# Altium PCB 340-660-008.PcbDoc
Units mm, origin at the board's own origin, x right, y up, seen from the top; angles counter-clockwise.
Board outline 21.35 x 16.64 mm, 2 copper layers (Top Layer, Bottom Layer), stack 1.569 mm thick; 37 components, 29 nets, 121 pads, 45 vias.
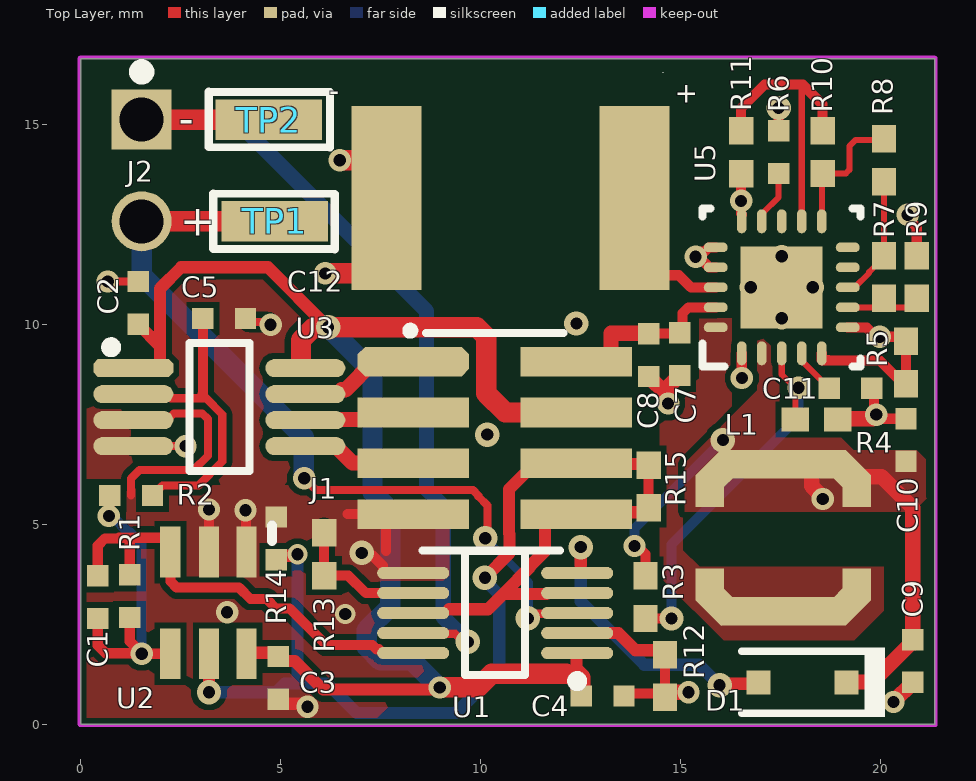
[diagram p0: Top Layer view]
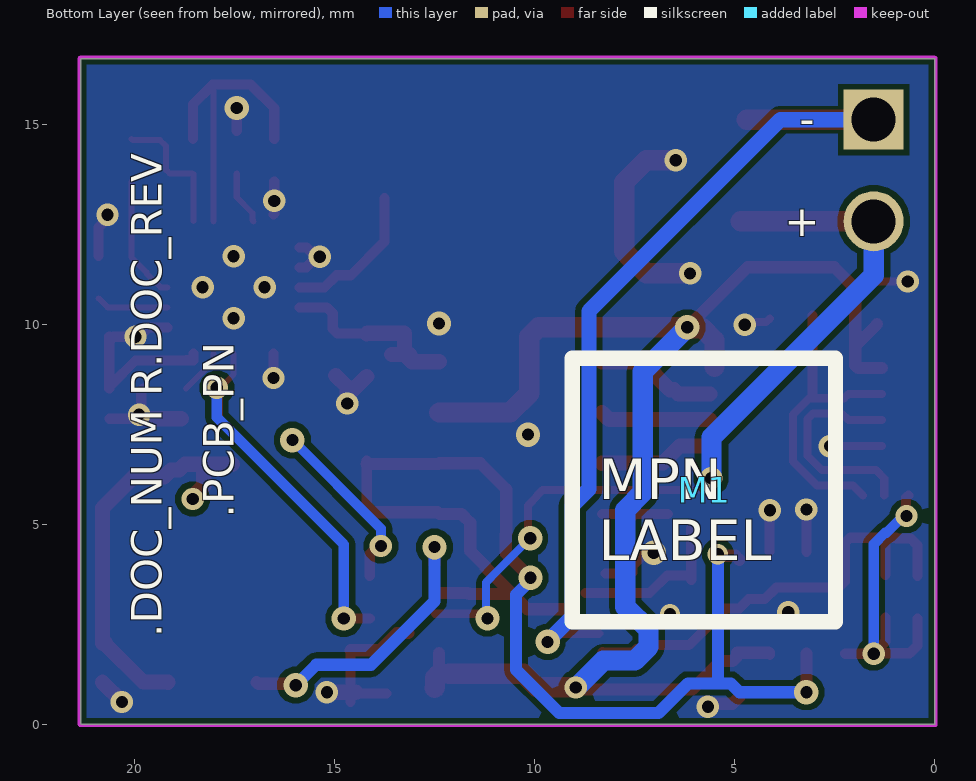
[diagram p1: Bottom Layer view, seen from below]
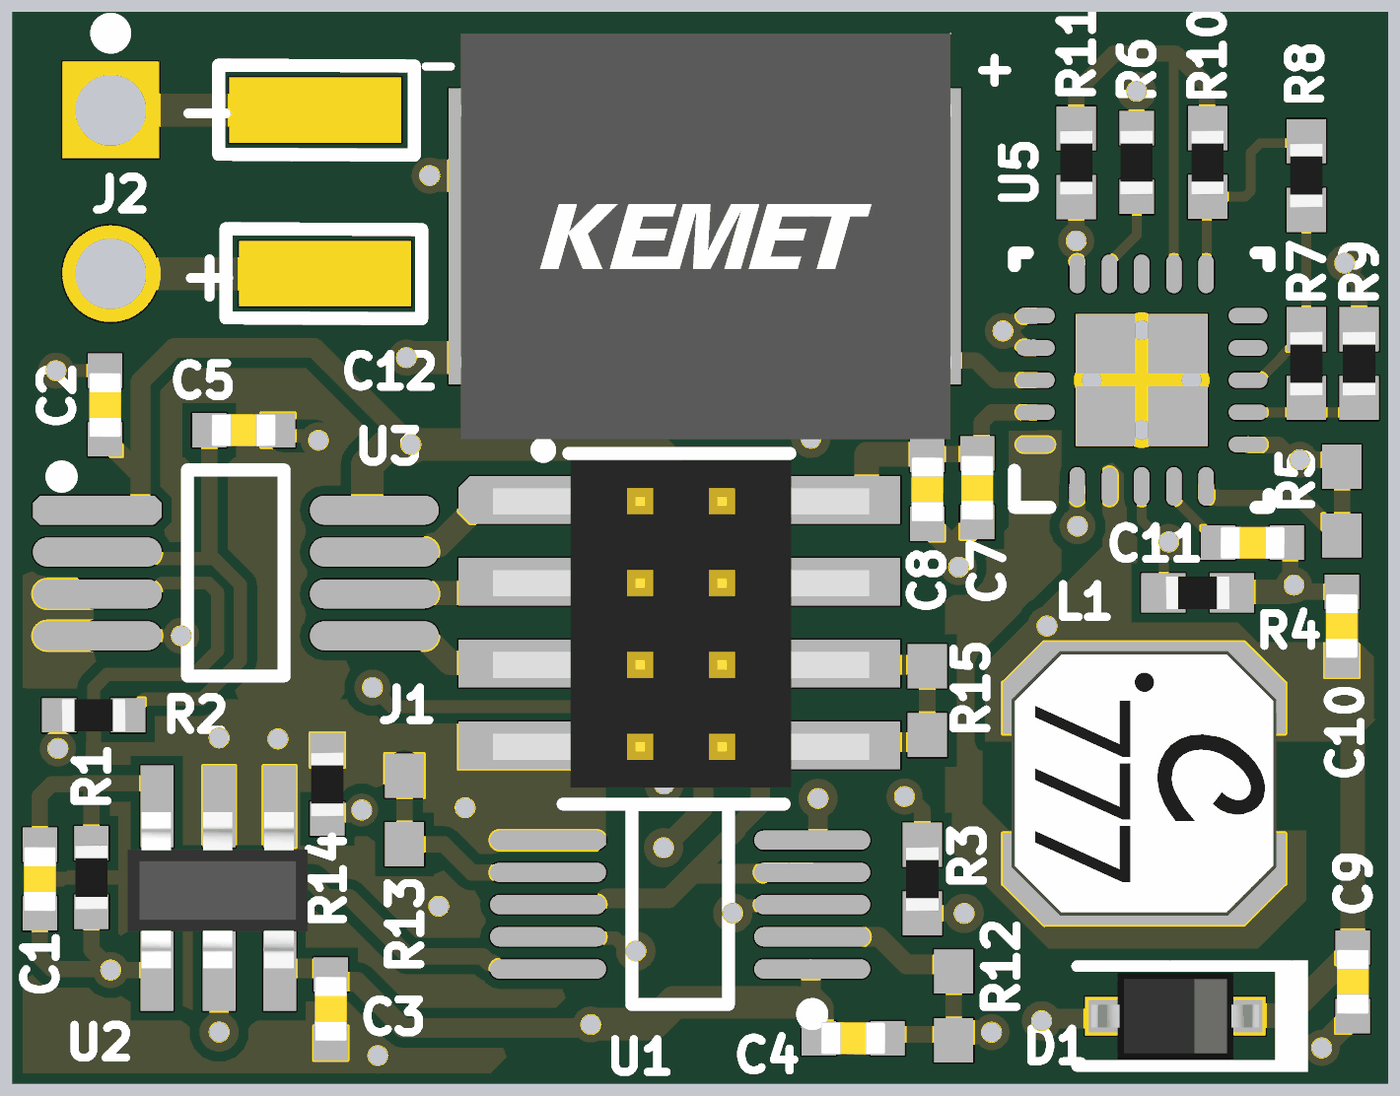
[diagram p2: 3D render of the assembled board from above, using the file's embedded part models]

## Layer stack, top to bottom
Top Solder: solder mask 0.0254, SM-001, Dk 4
Top Layer: signal copper 0.035
Dielectric 1: core 1.4986, Core-043, Dk 4.3
Bottom Layer: signal copper 0.035
Bottom Solder: solder mask 0.0254, SM-001, Dk 4

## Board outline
0,0 0,16.637 21.349,16.637 21.349,0

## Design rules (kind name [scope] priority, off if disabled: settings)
AssemblyTestPointUsage [All] p1 off:
AssemblyTestpoint [All] p1 off: testpointundercomponent=TRUE minsize=1.016 maxsize=2.54 preferedsize=1.524 minholesize=0 maxholesize=1.016 preferedholesize=0.813 testpointgrid=0.025 usegrid=TRUE gridtolerance=0 allowsidetop=TRUE allowsidebottom=TRUE
Clearance [All] p1: gap=0.152 ignorepadtopadclearanceinfootprint=TRUE except(0.127: Arc-Arc Arc-Track Arc-SMDPad Track-Track Track-SMDPad)
ComponentClearance [Not(HasFootprint('FID_TOP_BOT_39'))] p1: gap=0.254 collisioncheckmode=3 verticalgap=0 showdistances=FALSE
DiffPairsRouting [InDifferentialPairClass('All Differential Pairs')] p1: maxlimit=0.127 minlimit=0.127 mostfreqgap=0.127 toplayer_minwidth=0.203 toplayer_maxwidth=0.234 toplayer_prefwidth=0.179 bottomlayer_minwidth=0.203 bottomlayer_maxwidth=0.234 bottomlayer_prefwidth=0.179 impedanceprofiledriven=TRUE maxuncoupledlength=12.7
FabricationTestPointUsage [All] p1 off: valid=0 allowmultiple=FALSE
FabricationTestpoint [All] p1 off: side=3 testpointundercomponent=TRUE minsize=1.016 maxsize=2.54 preferedsize=1.524 minholesize=0 maxholesize=1.016 preferedholesize=0.813 testpointgrid=0.025 allowsidetop=TRUE allowsidebottom=TRUE usegrid=TRUE gridtolerance=0
HoleSize [All] p1: absolutevalues=TRUE maxlimit=5.08 minlimit=0.025 maxpercent=80.000 minpercent=20.000
HoleSize Testpoint [All] p2 off: absolutevalues=TRUE maxlimit=2.54 minlimit=0.025 maxpercent=80.000 minpercent=20.000
HoleSize TestPointUsage [All] p3 off: absolutevalues=TRUE maxlimit=2.54 minlimit=0.025 maxpercent=80.000 minpercent=20.000
MinimumAnnularRing [All] p1: minimumring=0.124
MinimumSolderMaskSliver [All] p1 off: minsoldermaskwidth=0.15
MinimumSolderMaskSliver SilkscreenOverComponentPads [All] p2 off: minsoldermaskwidth=0.254
NetAntennae [All] p1: netantennaetolerance=0.254
PlaneClearance [All] p1: clearance=0.381
PlaneConnect [All] p1: planeconnectstyle=Direct reliefexpansion=0.508 reliefentries=4 reliefconductorwidth=0.762 reliefairgap=0.254
PolygonConnect PolygonConnect_ConnectorPad [HasFootprint('JST_SM06B_SIDE') Or HasFootprint('JST_SM04B_SIDE')Or HasFootprint('JST_SM03B_SIDE') Or HasFootprint('JST_SM02B_SIDE') Or HasFootprint('JST_BM04B_TOP')] p1: connectstyle=Relief reliefconductorwidth=0.762 reliefentries=4 polygonreliefangle="90 Angle" airgapwidth=0.254
PolygonConnect [All] p2: connectstyle=Direct reliefconductorwidth=0.762 reliefentries=4 polygonreliefangle="45 Angle" airgapwidth=0.254
RoutingVias [All] p1: holewidth=0.305 width=0.66 viastyle="Through Hole" minholewidth=0.254 minwidth=0.508 maxholewidth=0.508 maxwidth=1.27
SilkToSilkClearance [All] p1 off: silktosilkclearance=0.254
SilkToSolderMaskClearance [IsPad] p1 off: minsilkscreentomaskgap=0.254 clearancetoexposedcopper=TRUE
SolderMaskExpansion [All] p1: expansion=0.025 istentingtop=FALSE
SupplyNets "Schematic Supply Nets" [InNet('GND')] p1: voltage=0.000
Width [All] p1: maxlimit=5.08 minlimit=0.152 preferedwidth=0.254 minimp=50.000000 maximp=50.000000 favimp=50.000000
17 further rules are at their usual default settings.

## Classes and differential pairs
component class S6: A1 M1 Z1
component class S5: C7 C8 C9 C10 C11 C12 D1 L1 R3 R4 R5 R6 R7 R8 R9 R10 R11 U5
component class S4: C1 C2 C3 C4 C5 R1 R2 R12 R13 R14 U1 U2 U3
component class 340-660-008: J1 J2 R15 TP1 TP2

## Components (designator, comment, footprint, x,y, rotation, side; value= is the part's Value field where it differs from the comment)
C1 "ECJ-0EC1H221J" 0402CAP 0.425,3.175 r90 top value=220pF
C2 "CL05A226MQ6ZUN8" 0402CAP 1.438,10.535 r270 top value=22uF
C3 "CL05A226MQ6ZUN8" 0402CAP 4.941,1.16 r90 top value=22uF
C4 "C1005X5R1V105K050BC" 0402CAP 13.049,0.703 r180 top value=1.0uF
C5 "ECJ-0EC1H221J" 0402CAP 3.588,10.143 r180 top value=220pF
C7 "GRM155R61A475MEAAD" 0402CAP 14.975,9.25 r270 top value=4.7uF
C8 "GMK105BJ104KV-F" 0402CAP 14.2,9.225 r270 top value=0.1uF
C9 "GRM155R61A475MEAAD" 0402CAP 20.803,1.579 r270 top value=4.7uF
C10 "GMK105BJ104KV-F" 0402CAP 20.633,7.103 r90 top value=0.1uF
C11 "ECJ-0EB1E103K" 0402CAP 19.247,8.396 r0 top value=0.01uF
C12 "T523H108M010APE070" CAP_CASEH 10.757,13.152 r0 top value="1000 uF"
D1 "1SS315TPH3F" sod-323 18.048,1.047 r180 top value=5V
J1 "FTS-104-01-L-DV" CONN_SAMTEC_FTS-104-01-L-DV 10.35,7.793 r270 top
J2 "PEC02SAAN" CONN_PEC02SAAN 1.524,13.843 r270 top
L1 "LPS4018-223MLC" LPS4018 17.562,4.66 r270 top value=22uH
M1 "MPN Label" LABEL_7x7mm 5.75,5.85 r180 bottom
R1 "RC0402FR-07100KL" 0402RES 1.225,3.2 r90 top value=100K
R2 "RC0402FR-07100RL" 0402RES 1.26,5.717 r180 top value=100
R3 "CRCW04024M12FKED" 0402 14.121,3.175 r90 top value=4.12Meg
R4 "CRCW04025M76FKED" 0402 18.395,7.618 r180 top value=5.76Meg
R5 "" 0402_Short 20.633,9.042 r270 top net-tie value=0.0
R6 "CR0402-J/-000GLF" 0402RES 17.447,14.3 r270 top value=0.0
R7 "CRCW04026M19FKED" 0402 20.082,11.177 r90 top value=6.19Meg
R8 "CRCW04023M09FKED" 0402 20.082,14.097 r270 top value=3.09Meg
R9 "CRCW04026M65FKED" 0402 20.9,11.177 r270 top value=6.65Meg
R10 "CRCW04023M57FKED" 0402 18.55,14.3 r270 top value=3.57Meg
R11 "CRCW04026M19FKED" 0402 16.51,14.297 r90 top value=6.19Meg
R12 "" 0402_Short 14.607,1.206 r270 top net-tie value=0.0
R13 "" 0402_Short 6.084,4.247 r90 top net-tie value=0.0
R14 "RC0402FR-07100KL" 0402RES 4.887,4.644 r90 top value=100K
R15 "" 0402_Short 14.199,5.945 r90 top net-tie value=0.0
TP1 "TEST POINT" TPSMTPAD 5.969,12.573 r180 top
TP2 "TEST POINT" TPSMTPAD 3.582,15.113 r0 top
U1 "ADG787BRMZ-500RL7" ADI-RM-10_N 10.362,2.778 r180 top
U2 "MAX9911EXT" SOT-23/6 4.147,4.302 r0 top
U3 "AD7683ARMZRL7" RM-8_M 3.466,7.927 r0 top
U5 "BQ25505RGRR" RGR0020A 17.526,10.921 r90 top

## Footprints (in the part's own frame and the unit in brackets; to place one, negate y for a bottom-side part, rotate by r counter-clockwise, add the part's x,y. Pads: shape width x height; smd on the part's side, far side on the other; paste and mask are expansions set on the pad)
0402 [mil]
  rect 27x24 smd: 1(-21,0) 2(21,0)
  body extent -20,-10 20,10, height 12
0402_Short [mil] "0402 package with PCB short"
  rect 27x24 smd: 1(-21,0) 2(21,0)
  Top Layer lines w10: 25.35,0.03 -25.29,0.03
0402CAP [mil]
  rect 21x21 smd: 1(-21,0) 2(21,0)
  body extent -20,-10 20,10, height 20
0402RES [mil]
  rect 21x21 smd: 1(-21,0) 2(21,0)
  body extent -20,-10 20,10, height 12
ADI-RM-10_N [mm] "SOP, 10-Leads, Body 3x3mm, Pitch 0.5mm, IPC Medium Density"
  oval 1.8x0.3 smd: 1(-2.05,1) 2(-2.05,0.5) 3(-2.05,0) 4(-2.05,-0.5) 5(-2.05,-1) 6(2.05,-1) 7(2.05,-0.5) 8(2.05,0) 9(2.05,0.5) 10(2.05,1)
  silkscreen extent -2.18,-1.55 0.75,1.82, body extent -1.55,-1.55 1.55,1.55, height 1.1
CAP_CASEH [mm]
  rect 1.753x4.6 smd: 1(3.086,0) 2(-3.112,0)
  silkscreen extent 3.8,3.15 3.81,3.15, body extent -3.8,-3.15 3.81,3.15, height 2
CONN_PEC02SAAN [mm] "SULLINS"
  rect 1.5x1.5 hole 1.1: 1(-1.27,0)
  round 1.5 hole 1.1: 2(1.27,0)
  silkscreen extent -2.59,-0.13 -2.34,0.13, body extent -2.54,-1.27 2.54,1.27, height 8.38
CONN_SAMTEC_FTS-104-01-L-DV [mm]
  oct 0.74x2.79 smd: 1(-1.27,-2.035)
  rect 0.74x2.79 smd: 2(-1.27,2.035) 3(0,-2.035) 4(0,2.035) 5(1.27,-2.035) 6(1.27,2.035) 7(2.54,-2.035) 8(2.54,2.035)
  silkscreen extent -2.14,-2.21 3.45,1.72, body extent -1.88,-2.9 3.2,2.95, height 4.29
LABEL_7x7mm [mm] "Box for MPN Lable, 7x7mm"
  silkscreen extent -3.31,-3.29 3.27,3.3
LPS4018 [mil]
  rect 28x123 smd: 1(-72.5,0) 2(72.5,0)
  rect 35.5x28 smd rot 45: 1(-64,64) 2(64.5,-63.5)
  rect 35.5x28 smd rot 135: 1(-64,-64) 2(64,64)
  rect 31.5x28 smd: 1(-46,72.5) 1(-46,-72.5) 2(46,72.5) 2(46,-72.5)
  body extent -81,-81 81,81, height 71
RGR0020A [mm] "QFN, 20-Leads, Body 3.5x3.5mm, Pitch 0.5mm, Thermal Pad 2.05x2.05mm, TI Recommended"
  oval 0.6x0.24 smd: 1(-1.65,1) 2(-1.65,0.5) 3(-1.65,0) 4(-1.65,-0.5) 5(-1.65,-1) 11(1.65,-1) 12(1.65,-0.5) 13(1.65,0) 14(1.65,0.5) 15(1.65,1)
  oval 0.24x0.6 smd: 6(-1,-1.65) 7(-0.5,-1.65) 8(0,-1.65) 9(0.5,-1.65) 10(1,-1.65) 16(1,1.65) 17(0.5,1.65) 18(0,1.65) 19(-0.5,1.65) 20(-1,1.65)
  rect 2.05x2.05 smd paste-1.025: 21(0,0)
  silkscreen extent -1.98,-1.98 1.98,1.98, body extent -1.83,-1.83 1.83,1.83, height 1.01
RM-8_M [mm] "TSOP, 8-Leads, Body 3x3mm, Pitch 0.65mm, IPC Low Density"
  oct 2x0.45 smd: 1(-2.15,0.975)
  oval 2x0.45 smd: 2(-2.15,0.325) 3(-2.15,-0.325) 4(-2.15,-0.975) 5(2.15,-0.975) 6(2.15,-0.325) 7(2.15,0.325) 8(2.15,0.975)
  silkscreen extent -2.83,-1.6 0.75,1.62, body extent -1.6,-1.6 1.6,1.6, height 1.1
sod-323 [mm] "NXP recommended land pattern"
  rect 0.6x0.6 smd paste-0.05: 1(-1.1,0) 2(1.1,0)
  silkscreen extent -2.06,-0.86 1.53,0.86, body extent -1.3,-0.67 1.3,0.68, height 1.1
SOT-23/6 [mil]
  rect 20x50 smd: 1(0,0) 2(-37,0) 3(-75,0) 4(-75,-100) 5(-37,-100) 6(0,-100)
  silkscreen extent 25,11 25,26, body extent -93,-99 17,-3, height 43
TPSMTPAD [mil] "0.105\"x0.040\" rectangular SMT Pad for Test Point"
  rect 105x40 smd paste-27.56: 1(44,0)
  silkscreen extent -15,-27 104,27

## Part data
C1 C5: library part CAP_0402_220pF_NP0_50V, "CAP 220PF 50V CERAMIC 0402 SMD", Supplier Part Number 1=PCC221CQCT-ND, Voltage=50V
C2 C3: library part CAP_0402_22uF_X5R_6.3V, "22µF ±20% 6.3V Ceramic Capacitor X5R 0402 (1005 Metric)", Supplier Part Number 1=1276-6804-1-ND, Voltage=6.3V
C4: library part CAP_0402_1uF_X5R_35V, "CAP CER 1UF 35V X5R 0402", Supplier Part Number 1=810-C1005X5R1V105K, Voltage=35V
C7 C9: library part CAP_0402_4.7uF_X5R_10V, "4.7µF ±20% 10V Ceramic Capacitor X5R 0402 (1005 Metric)", Supplier Part Number 1=490-14306-1-ND, Voltage=10V
C8 C10: library part CAP_0402_0.1uF_X5R_35V, "CAP CER .10UF 35V X5R 0402", Supplier Part Number 1=587-1994-1-ND, Voltage=35V
C11: library part CAP_0402_0.01uF_X7R_25V_2, "CAP .01UF 25V CERAMIC X7R 0402", Supplier Part Number 1=PCC2270CT-ND, Voltage=25V
C12: library part CAP_TANT_CASE_H_1000uF_10V_20%_1, "1000µF Molded Tantalum Polymer Capacitor 10V 2924 (7360 Metric) 70mOhm @ 100kHz", Supplier Part Number 1="Mouser -  80-T523H108M010APE70", Tolerance Rated Capacitance="-20 to 20%", Voltage="10 V"
D1: "Diode, Schottky, 5V, 0.03A, SOD-323", Manufacturer=Toshiba, Supplier Part Number 1=1SS315TPH3FCT-ND, Value1=0.03A, Value2=0.38V
J1: library part CONN_Samtec_FTS-104-01-L-DV, "2x4 0.050\" Surface Mount Micro Terminal Strip", Supplier Part Number 1=SAM13892CT-ND
J2: "Header, 100mil, 2x1, Tin, TH", Manufacturer="Sullins Connector Solutions", Supplier Part Number 1=S1012E-02-ND
L1: library part LPS4018-223MLB, "Inductor, Shielded Drum Core, Ferrite, 22 µH, 0.83 A, 0.36 ohm, SMD", Manufacturer=Coilcraft, Value1="0.36 ohm", Value2=0.83A, ValueDisplayed=22µH
M1: library part Label_MPN, "Serial Number Label Placeholder"
R1 R14: library part Res_0402_100K_1%, "RES 100K OHM 1/16W 1% 0402 SMD", Supplier Part Number 1=311-100KLRCT-ND
R2: library part Res_0402_100_1%_1, "RES SMD 100 OHM 1% 1/16W 0402"
R3: "RES, 4.12 M, 1%, 0.063 W, 0402", Manufacturer=Vishay-Dale, Power_W=0.063, Supplier Part Number 1=541-4.12MLCT-ND, TempCo="100 ppm/C", Tolerance_%=1, Value1=1%, Value2=0.063W, Value_Code=4M12, ValueDisplayed=4.12M
R4: "RES, 5.76 M, 1%, 0.063 W, 0402", Manufacturer=Vishay-Dale, Power_W=0.063, Supplier Part Number 1=71-CRCW04025M76FKED, TempCo="100 ppm/C", Tolerance_%=1, Value1=1%, Value2=0.063W, Value_Code=5M76, ValueDisplayed=5.76M
R5 R12 R13 R15: library part Res_0402_Short, "Resistor footpring with PCB short in footprint; cut to use as regular footprint"
R6: library part Res_0402_0.0_5%_2, "RES ZERO OHM 1/10W 5% 0402 SMD", Supplier Part Number 1=652-CR0402-J/-000GLF
R7 R11: "RES, 6.19 M, 1%, 0.063 W, 0402", Manufacturer=Vishay-Dale, Power_W=0.063, Supplier Part Number 1=71-CRCW04026M19FKED, TempCo="100 ppm/C", Tolerance_%=1, Value1=1%, Value2=0.063W, Value_Code=6M19, ValueDisplayed=6.19M
R8: "RES, 3.09 M, 1%, 0.063 W, 0402", Manufacturer=Vishay-Dale, Power_W=0.063, Supplier Part Number 1=541-3.09MLCT-ND, TempCo="100 ppm/C", Tolerance_%=1, Value1=1%, Value2=0.063W, Value_Code=3M09, ValueDisplayed=3.09M
R9: "RES, 6.65 M, 1%, 0.063 W, 0402", Manufacturer=Vishay-Dale, Power_W=0.063, Supplier Part Number 1=71-CRCW04026M65FKED, TempCo="100 ppm/C", Tolerance_%=1, Value1=1%, Value2=0.063W, Value_Code=6M65, ValueDisplayed=6.65M
R10: "RES, 3.57 M, 1%, 0.063 W, 0402", Manufacturer=Vishay-Dale, Power_W=0.063, Supplier Part Number 1=541-3.57MLCT-ND, TempCo="100 ppm/C", Tolerance_%=1, Value1=1%, Value2=0.063W, Value_Code=3M57, ValueDisplayed=3.57M
TP1 TP2: library part Test_Point_SMT, "Test Point SMT"
U1: library part CMP-0790-00114-1, "2.5 Ohm CMOS Low Power Dual 2:1 Mux / Demux USB 1.1 Switch, -40 to 85 degC, 10-pin SOP (RM-10), Reel", Manufacturer="Analog Devices", Power Dissipation=5.5uW
U2: Package=None
U3: library part CMP-0313-01716-2, "Single 16-Bit PulSAR Analog-to-Digital Converter with Serial, SPI Interface, 100KSPS, -40 to +85 degC, RM-8, Pb-Free, Reel", Generic Part Number=AD7683, Manufacturer="Analog Devices"
U5: "Ultra Low Power Boost Converter with Battery Management for Energy Harvester Applications, RGR0020A", Alternate Manufacturer="Texas Instruments", Alternate PartNumber=BQ25505RGRT

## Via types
v1: diameter 0.559, hole 0.305, Top Layer to Bottom Layer, tented both sides, 29 vias
v2: diameter 0.61, hole 0.305, Top Layer to Bottom Layer, tented both sides, 14 vias
v3: diameter 0.508, hole 0.305, Top Layer to Bottom Layer, tented both sides, 2 vias

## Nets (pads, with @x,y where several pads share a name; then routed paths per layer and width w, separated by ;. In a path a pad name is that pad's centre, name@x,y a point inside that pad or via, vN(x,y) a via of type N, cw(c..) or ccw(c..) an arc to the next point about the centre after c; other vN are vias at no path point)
ENABLE: J1.6 R14.1 R15.2 U2.5 | length 21.6
  Top Layer w0.305: v2(3.207,0.8) U2.5 ; R14.1 4.985,4.209 5.381,4.209 v3(5.42,4.247) ; v2(10.105,3.661) 10.722,4.278 10.722,4.756 10.711,4.767 10.711,5.874 11.36,6.523 J1.6 12.407,6.501 R15.2@14.199,6.501
  Bottom Layer w0.305: v2(3.207,0.8) 4.882,0.8 5.1,1.018 5.501,1.018 ; v3(5.42,4.247) 5.42,1.099 5.501,1.018 ; v2(10.105,3.661) 10.105,3.598 10.465,3.238 10.465,1.361 9.384,0.279 6.903,0.279 6.164,1.018 5.501,1.018
ENABLE2: J1.8 R15.1 U1.4 U1.8 | length 8.3
  Top Layer w0.305: 9.213,2.873 10.18,2.873 10.561,3.255 ; U1.4 11.667,3.278 11.644,3.255 10.561,3.255 ; R15.1 14.16,5.411 14.046,5.298 12.43,5.298 J1.8 11.826,5.253 11.608,5.035 11.608,4.331 11.233,3.956 11.233,3.927 10.561,3.255
GND: C2.1 C3.1 C4.1 C5.1 C7.2 C8.2 C9.2 C10.2 C11.2 C12.2 J1.7 R4.1 R5.1 R6.1 R9.1 R11.1 R12.2 R13.2 R14.2 U1.6 U2.1 U2.2 U3.3 U3.4 U5.1 U5.6 U5.15 U5.16 U5.17 U5.21 | length 32.7
  Top Layer w0.203: v1(0.675,11.068) C2.1 ; 1.26,5.717 1.26,6.147 1.466,6.353 2.823,6.353 3.182,6.712 3.182,7.63 3.04,7.772 2.327,7.772 2.158,7.602 U3.3 ; U3.4 v1(2.62,6.952) ; C5.1 4.21,10.055 4.681,10.055 v1(4.749,9.987)
  Top Layer w0.254: U2.2 v1(3.207,5.367) ; v1(4.12,5.35) 4.133,5.336 U2.1@4.133,4.316 ; 6.666,5.253 J1.7@7.49,5.253 ; v2(7.025,4.281) 7.093,4.213 7.303,4.213 7.554,3.962 7.554,3.8 7.59,3.763 U1.6@8.226,3.763 ; 7.633,4.333 7.633,5.11 J1.7@7.49,5.253 ; J1.7 J1.7@7.49,5.253 ; C4.1@13.71,0.763 R12.2@14.474,0.763 ; v1(15.373,11.685) 15.446,11.685 15.71,11.421 U5.17 ; v1@15.395,11.685 15.531,11.82 15.609,11.82 15.71,11.921 U5.16 ; R11.1@16.51,13.564 16.51,12.764 U5.15@16.53,12.744 ; U5.1 16.526,8.734 16.53,8.73 v1(16.53,8.653) ; R6.1 v2(17.447,15.406) ; U5.6 19.183,9.914 19.653,9.914 19.882,9.685 v1(19.978,9.685) 20.524,9.685 R5.1 ; C11.2 19.835,8.342 19.835,7.793 v1(19.889,7.739) 19.904,7.739 20.006,7.636 C10.2 ; v1(20.678,12.737) 20.678,12.646 20.9,12.424 R9.1
  Top Layer w0.305: C3.1@4.887,0.724 4.887,0.681 5.055,0.512 5.522,0.512 5.6,0.434 v1(5.669,0.434)
  Top Layer w0.381: C8.2 v1@14.651,8.241 ; R12.2@14.474,0.797 v1(15.195,0.797) ; v1(14.685,8.016) 14.685,8.427 C7.2 ; R4.1@18.834,7.636 19.801,7.636 v1@19.904,7.739 ; v1(20.32,0.554) 20.32,0.563 C9.2
  Top Layer w0.508: v1(6.113,11.271) 7.211,11.271 7.757,11.817 7.757,13.551 7.211,14.097 v1(6.475,14.097)
  other v1: 3.66,2.799 17.526,10.146 16.751,10.921 18.301,10.921 17.526,11.696 16.509,13.082
  other v2: 10.166,7.239 12.392,10.017
  other v3: 6.616,2.753
HARVSTR_OUT: C7.1 C8.1 J1.2 U5.19 | length 5
  Top Layer w0.254: C8.1 14.212,9.771 14.935,9.771 15.046,9.883 15.046,10.272 15.195,10.421 U5.19
  Top Layer w0.381: J1.2 13.078,9.063 J1.2@13.257,9.243 ; J1.2@13.123,9.243 J1.2@13.257,9.243 ; J1.2@13.57,9.243 J1.2@13.257,9.243 ; C8.1 14.188,9.771 13.257,9.771 J1.2@13.257,9.243
I_SOL: C1.2 R1.2 U1.10 U2.3 | length 11.4
  Top Layer w0.254: C1.2 0.425,4.464 0.606,4.644 0.948,4.644 0.963,4.66 1.306,4.66 ; R1.2 1.225,4.579 1.306,4.66 ; U1.10@8.3,1.8 8.288,1.787 7.541,1.787 7.454,1.874 7.395,1.874 7.291,1.978 6.139,1.978 5.224,2.894 4.882,2.894 4.648,3.128 4.245,3.128 3.96,3.413 2.402,3.413 2.248,3.568 2.248,4.296 U2.3 2.242,4.533 2.115,4.66 1.306,4.66
LBOOST: L1.2 U5.20
nEN_bq: R5.2 U5.5 | length 2.5
  Top Layer w0.254: U5.5 18.526,9.105 18.533,9.098 18.699,9.098 18.706,9.091 19.978,9.091 R5.2@20.597,8.473
NetD1_2: D1.2 U1.5 | length 7.1
  Top Layer w0.305: 12.501,3.978 12.503,3.981 v2(12.503,4.426) ; v2(15.972,0.975) 16.009,1.011 16.912,1.011 D1.2
  Bottom Layer w0.305: v2(12.503,4.426) 12.503,3.073 14.089,1.488 15.459,1.488 v2(15.972,0.975)
NetJ1_1: J1.1 U3.7 | length 3
  Top Layer w0.381: U3.7 6.41,8.252 6.517,8.36 6.616,8.36 7.319,9.063 J1.1
NetJ1_3: J1.3 U3.6 | length 2.8
  Top Layer w0.381: U3.6 5.629,7.615 8.137,7.615 J1.3
NetJ1_5: J1.5 U3.5 | length 2.9
  Top Layer w0.381: U3.5 6.372,6.952 6.792,6.532 8.306,6.532 J1.5
NetR3_1: R3.1 R4.2 U5.3 | length 9.6
  Top Layer w0.152: U5.3 17.526,8.742 17.859,8.409 v1(17.946,8.409) 17.868,8.332 17.868,7.625 R4.2
  Top Layer w0.254: R3.1 v2(14.771,2.642)
  Bottom Layer w0.254: v2(14.771,2.642) 14.771,4.496 17.946,7.671 v1(17.946,8.409)
NetR6_2: R6.2 U5.14 | length 1.4
  Top Layer w0.152: U5.14 17.055,12.6 17.055,12.78 17.447,13.172 R6.2
NetR12_1: R12.1 U1.2 | length 1.6
  Top Layer w0.305: U1.2@13.16,2.276 13.444,2.276 13.871,1.849 R12.1@14.608,1.849
NetR13_1: R13.1 U1.7 | length 2.8
  Top Layer w0.254: R13.1 6.693,3.714 7.128,3.278 U1.7@8.723,3.278
OK_HYST: R8.1 R10.2 U5.11 | length 3.4
  Top Layer w0.152: U5.11@18.534,12.579 18.534,13.751 R10.2 19.126,13.767 19.215,13.856 19.215,14.449 19.366,14.6 20.052,14.6 R8.1
OK_PROG: R10.1 R11.2 U5.12 | length 7.6
  Top Layer w0.152: U5.12 18.026,15.989
  Top Layer w0.254: R11.2@16.512,14.632 16.512,15.406 17.096,15.99 18.05,15.99 18.542,15.498 R10.1@18.542,14.63 ; 18.026,15.989 18.051,15.989
SOLAR_A: J2.2 TP1.1 U1.3 | length 21
  Top Layer w0.203: v1(5.587,6.148) 5.884,5.852 9.805,5.852 9.939,5.718 9.939,5.699 10.166,5.471 10.166,4.644 10.161,4.649 v2(10.113,4.649) ; v2(11.179,2.646) 11.289,2.646 11.403,2.76 U1.3@12.493,2.76
  Top Layer w0.508: J2.2 TP1.1
  Bottom Layer w0.203: v2(10.113,4.649) 11.075,3.687 11.075,3.679 11.212,3.541 11.212,2.679 v2(11.179,2.646)
  Bottom Layer w0.508: J2.2 1.524,11.227 5.578,7.173 5.578,6.158 v1(5.587,6.148)
SOLAR_C: J2.1 TP2.1 U1.9 | length 22.4
  Top Layer w0.203: U1.9@8.379,2.271 8.39,2.26 9.362,2.26 9.565,2.056 v2(9.675,2.056)
  Top Layer w0.508: J2.1 TP2.1
  Bottom Layer w0.381: J2.1 3.857,15.113 8.644,10.326 8.644,5.875 9.061,5.457 9.061,2.682 9.675,2.068 v2(9.675,2.056)
V_SOL: C5.2 R2.1 U3.2 | length 7.8
  Top Layer w0.203: U3.2 2.158,8.252 2.26,8.15 3.129,8.15 ; R2.1 2.044,5.968 2.941,5.968 3.537,6.565 3.537,7.741 3.129,8.15 ; 3.027,8.252 3.129,8.15
  Top Layer w0.254: 3.055,9.619 C5.2@3.055,10.212 ; 3.055,8.252 3.055,9.619
V_TIA: C1.1 R1.1 R2.2 U2.4 | length 8
  Top Layer w0.254: C1.1 0.425,1.975 0.625,1.775 1.511,1.775 v1(1.524,1.762) ; R2.2@0.658,5.717 0.715,5.66 0.715,5.214 v1(0.704,5.203) ; R1.1 1.225,2.075 1.524,1.776 v1(1.524,1.762) ; U2.4 v1(1.524,1.762)
  Bottom Layer w0.254: v1(0.704,5.203) 0.787,5.203 1.204,4.785 1.24,4.785 1.524,4.501 v1(1.524,1.762)
VB_PRI_ON: U5.10
VB_SEC_ON: U5.9
VBAT_OV: R7.1 R9.2 U5.7 | length 1.8
  Top Layer w0.152: U5.7 20.678,10.421 R9.2
VBAT_SEC: C12.1 U5.18 | length 3.7
  Top Layer w0.254: C12.1@13.757,13.152 13.757,12.059 14.592,11.223 14.952,11.223 15.254,10.921 U5.18
VCC: C2.2 C3.2 C4.2 J1.4 U1.1 U2.6 U3.1 U3.8 | length 38.5
  Top Layer w0.254: U2.6@4.12,1.735 U2.6
  Top Layer w0.305: U3.1 1.916,8.902 1.983,8.969 1.983,9.456 ; C2.2 1.983,9.456 ; 1.983,10.685 1.983,9.456 ; 1.984,10.685 1.984,10.894 2.511,11.421 4.682,11.421 v2@6.183,9.92 ; U2.6@4.147,1.788 4.941,1.788 C3.2 5.055,1.579 5.35,1.579 6.065,0.864 8.743,0.864 8.747,0.868 8.926,0.868 v1(8.975,0.916) ; 12.392,1.262 U1.1@12.392,1.778
  Top Layer w0.508: U3.8@5.506,8.931 5.506,9.604 5.804,9.902 6.165,9.902 v2(6.184,9.921) 9.903,9.921 10.139,9.685 10.139,8.267 10.613,7.793 J1.4 ; v1(8.975,0.916) 8.985,0.926 9.935,0.926 10.27,1.262 12.145,1.262 ; 12.392,1.262 12.491,1.163 12.491,0.916 C4.2@12.503,0.903
  Bottom Layer w0.508: v2(6.184,9.921) 7.296,8.809 7.296,5.794 7.736,5.353 7.736,2.939 7.152,2.355 7.152,1.934 7.494,1.592 8.286,1.592 8.961,0.916 v1(8.975,0.916)
VIN_bq: C9.1 C10.1 D1.1 L1.1 R3.2 U5.2 | length 15.2
  Top Layer w0.254: v1(13.844,4.456) 13.912,4.456 14.121,4.247 R3.2
  Top Layer w0.381: v1(18.55,5.63) 18.55,5.678 18.275,5.953 18.275,6.336 18.11,6.501 17.562,6.501 18.738,6.501 18.887,6.353 19.09,6.353 19.255,6.187 20.021,6.187 20.803,5.405 C9.1@20.803,2.015 ; D1.1@19.17,1.047 19.178,1.055 19.786,1.055 20.726,1.996 20.726,2.036 C9.1
  Bottom Layer w0.254: v1(13.844,4.456) 13.844,4.891 v2(16.056,7.103)
VRDIV: R7.2 R8.2 U5.8 | length 3.1
  Top Layer w0.152: U5.8 19.351,10.921 19.707,11.277 19.707,11.297 20.082,11.672 R7.2 R8.2
VREF_SAMP: C11.1 U5.4 | length 1.2
  Top Layer w0.152: U5.4 18.026,9.084 C11.1
pads on no net: U5.13

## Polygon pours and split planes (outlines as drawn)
GND on Top Layer "GND_L01_P003" (solid, pour order 3): 9.213,5.968 9.213,1.953 7.26,0 0,0 0,5.968
GND on Top Layer "GND_L01_P005" (solid, pour order 5): 0,5.968 6.616,5.968 6.616,10.021 4.965,11.672 2.564,11.672 0,9.108
LBOOST on Top Layer "LBOOST_L01_P001" (solid, remove dead copper, pour order 1): 15.463,10.146 16.282,10.146 16.282,7.854 15.053,6.625 15.053,4.348 15.471,3.93 20.082,3.93 20.082,2.841 19.334,2.094 16.074,2.094 14.474,3.694 14.474,7.664 15.463,8.653
VIN_bq on Top Layer "VIN_BQ_L01_P000" (solid, remove dead copper, pour order 0): 20.814,5.309 21.157,5.652 21.132,5.677 21.132,6.62 20.9,6.852 19.326,6.852 18.228,7.95 17.458,7.95 17.458,9.253 17.026,9.685 16.916,9.685 16.916,8.345 15.096,6.525 15.096,5.309
GND on Bottom Layer "GND_L02_P002" (solid, remove dead copper, pour order 2): 0,-0.038 cw(c0,0) -0.038,0 -0.038,16.637 cw(c0,16.637) 0,16.675 21.349,16.675 cw(c21.349,16.637) 21.387,16.637 21.387,0 cw(c21.349,0) 21.349,-0.038

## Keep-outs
Keep-Out Layer:
  lines w0.076: -0.038,0 ccw(c0,0) 0,-0.038 ; -0.038,0 ccw(c0,0) 0,-0.038 ; -0.038,0 -0.038,16.637 ; -0.038,16.637 cw(c0,16.637) 0,16.675 ; -0.038,16.637 cw(c0,16.637) 0,16.675 ; 0,-0.038 21.349,-0.038 ; 0,16.675 21.349,16.675 ; 21.349,-0.038 ccw(c21.349,0) 21.387,0 ; 21.349,-0.038 ccw(c21.349,0) 21.387,0 ; 21.349,16.675 cw(c21.349,16.637) 21.387,16.637 ; 21.349,16.675 cw(c21.349,16.637) 21.387,16.637 ; 21.387,0 21.387,16.637

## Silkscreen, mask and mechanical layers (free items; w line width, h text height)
Top Overlay:
  text "-" at 2.45,14.764 h0.76
  text "+" at 2.486,12.208 h0.76
Bottom Overlay:
  text "-" at 3.002,14.747 h0.76
  text "+" at 2.877,12.2 h0.76
  text ".PCB_PN" at 17.526,5.162 h0.76 r270
  text ".DOC_NUM R.DOC_REV" at 19.325,2.175 h0.76 r270
Outline:
  lines w0.076: -0.038,0 ccw(c0,0) 0,-0.038 ; -0.038,0 ccw(c0,0) 0,-0.038 ; -0.038,0 -0.038,16.637 ; -0.038,16.637 cw(c0,16.637) 0,16.675 ; -0.038,16.637 cw(c0,16.637) 0,16.675 ; 0,-0.038 21.349,-0.038 ; 0,16.675 21.349,16.675 ; 21.349,-0.038 ccw(c21.349,0) 21.387,0 ; 21.349,-0.038 ccw(c21.349,0) 21.387,0 ; 21.349,16.675 cw(c21.349,16.637) 21.387,16.637 ; 21.349,16.675 cw(c21.349,16.637) 21.387,16.637 ; 21.387,0 21.387,16.637
Fab Notes:
  text ".Print_Date" at 41.163,85.944 h1.02
  text ".Print_Time" at 60.741,85.787 h1.02
  text "FABRICATION NOTES" at 41.049,83.604 h1.52
  text "1. PCB CONSTRUCTION: 2 LAYERS, AS SHOWN IN STACK-UP DETAIL." at 48.035,81.545 h1.52
  text "2. MATERIAL" at 48.033,79.117 h1.52
  text "A. LAMINATE: 0.059\" +/- 10%" at 52.432,76.256 h1.52
  text "B. 1 OZ COPPER ON EXTERNAL LAYERS, PLATED TO 1.5 OZ MIN. (2 OZ PREFERRED) FINISHED WEIGHT." at 52.282,72.834 h1.52
  text "C. TOLERANCE: PER IPC-D-275" at 50.257,70.377 h1.52
  text "D. BONDING INTERLAYERS: PER IPC-2-110" at 52.282,69.002 h1.52
  text "E. ELECTROLESS NICKEL IMMERSION GOLD (ENIG) FINISH." at 52.107,66.134 h1.52
  text "3. PROCESSING TOLERANCES:" at 48.26,64.777 h1.52
  text "A. CONDUCTIVE PATTERN FRONT TO BACK, REGISTRATION +/- 0.005\"" at 52.911,62.718 h1.52
  text "B. MINIMUM AVERAGE PLATED THROUGH HOLE THICKNESS 0.001\" WITH NO READING LESS THAN 0.0004\"" at 52.911,60.306 h1.52
  text "C. FINISHED HOLE TOLERANCES AS FOLLOWS UNLESS OTHERWISE INDICATED:" at 52.911,58.071 h1.52
  text "PLATED +/- 0.003" at 57.044,55.836 h1.52
  text "NON-PLATED: +/- 0.003" at 57.047,53.601 h1.52
  text "D. MINIMUM ANNULAR RING FOR VIAS 0.006\"" at 52.911,51.365 h1.52
  text "E. MINIMUM CONDUCTOR WIDTH 0.008\"" at 52.911,49.13 h1.52
  text "F. MINIMUM INTER-CONDUCTOR SPACE 0.006\"" at 52.911,46.895 h1.52
  text "4. DIMENSIONS:" at 48.357,44.302 h1.52
  text "A. INSIDE CORNER RADII <= 1.0MM" at 52.857,41.902 h1.52
  text "5. WARP AND TWIST:" at 48.582,39.352 h1.52
  text "A. WITHIN 0.010\" PER INCH MAX" at 52.678,37.051 h1.52
  text "D. SOLDER MASK TO ETCH REGISTRATION WITHIN 0.003\" TOTAL" at 53.011,35.132 h1.52
  text "6. SOLDER MASK" at 41.678,31.065 h1.52
  text "A. LPI SMOBC 2 SIDE, PER IPC-SM-840, REV C, CLASS H" at 46.329,29.006 h1.52
  text "B. COLOR = GREEN" at 46.329,26.594 h1.52
  text "C. NO MASK ALLOWED ON TERMINAL AREAS, COMPONENT SOLDER PADS & TEST POINTS" at 46.332,23.977 h1.52
  text "D. MASK OPENINGS THAT ARE 1:1 WITH THE COPPER PADS SHOULD BE ADJUSTED BY THE FABRICATOR AS NEEDED" at 46.329,19.961 h1.52
  text "7. SILKSCREEN:" at 41.678,17.653 h1.52
  text "A. NON-CONDUCTIVE WHITE EPOXY INK ON BOTH SIDES" at 46.032,15.752 h1.52
  text "B. NOMENCLATURE SHALL BE COMPLETE AND LEGIBLE PER IPC-D-275 AND IPC-A-600" at 46.157,13.077 h1.52
  text "ON SOLDER SIDE OF PCB ANYWHERE FOR EACH LOT" at 48.082,11.327 h1.52
  text "C. MERGE SOLDERMASK AND SILKSCREEN - NO SILKSCREEN ALLOWED ON EXPOSED COPPER" at 46.282,8.952 h1.52
  text "9. BOARDS TO BE 100% TESTED TO IPC-D-3506A NETLIST - NO REWORK" at 40.975,6.55 h1.52
  text "For any questions please contact Mikhail Fridberg - 781-327-2037 - fridberg@adspconsulting.com" at 41.4,3.775 h1.52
